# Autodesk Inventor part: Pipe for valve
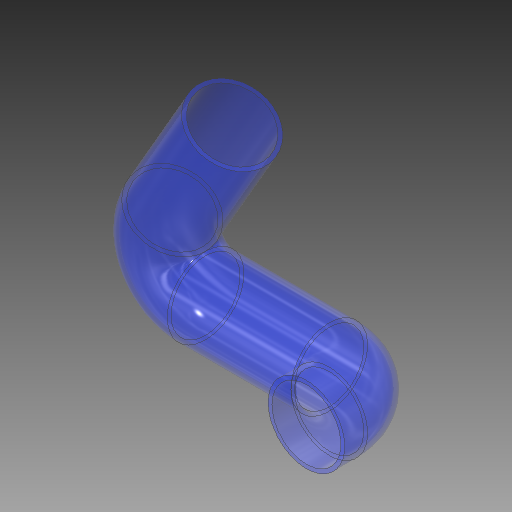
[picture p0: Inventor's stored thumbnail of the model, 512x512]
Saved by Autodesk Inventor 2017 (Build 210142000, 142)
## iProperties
Created: 2020-04
Part Number: Pipe for valve
Material: Polycarbonate, Clear
Document SubType Name: Modeling
Designer: user
Density: 1.2 g/cm^3
Appearance: Polycarbonate - Clear
Mass: 7.59922 g
Surface Area: 127.847 cm^2
Volume: 6.33268 cm^3
Author: user
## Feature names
1. Sweep1
## Parameters: d0 = 15.96 mm, d1 = 42.28 mm, d4 = 60 deg, d6 = 1 mm, d7 = 0, d8 = 0
